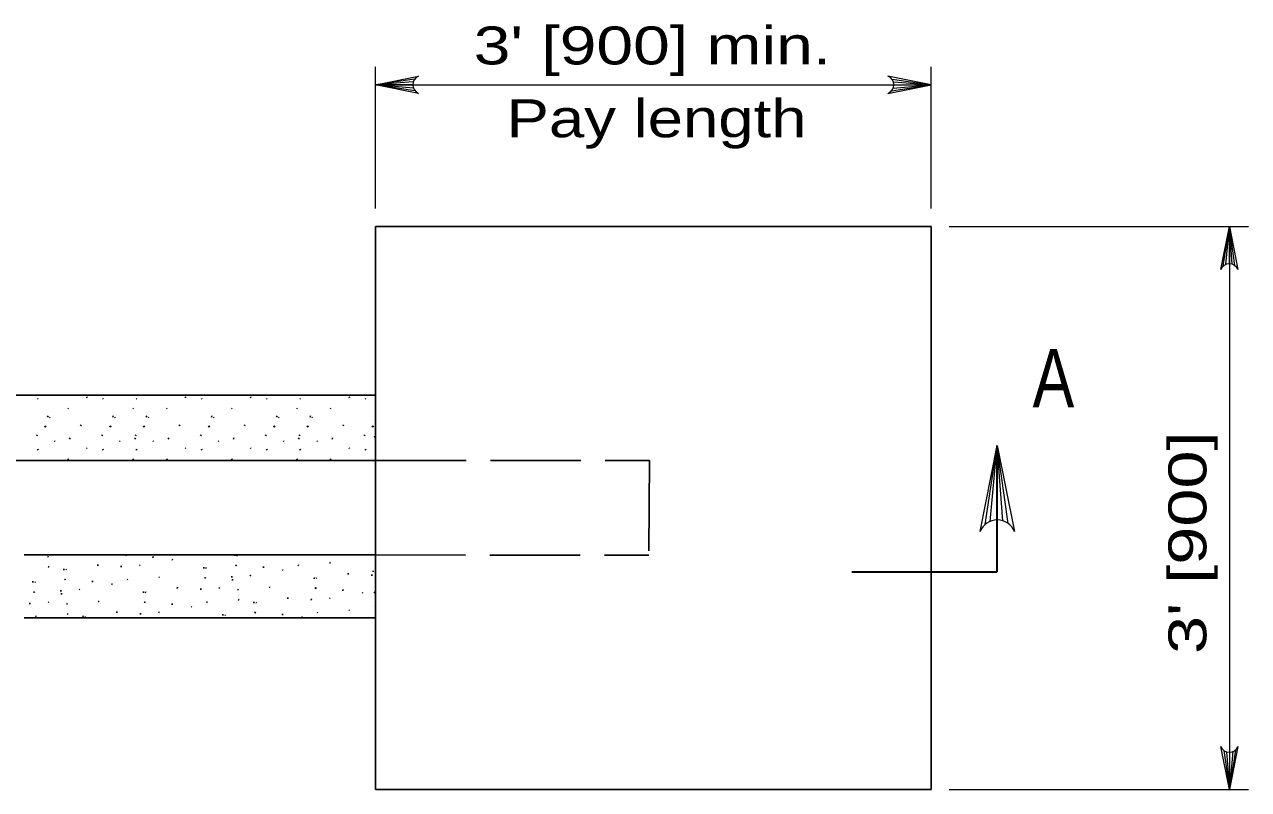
# Model space of a CAD drawing. Extents: x 1083.1 to 1117.1, y 697.4 to 741.4.
# Drawn here: x 1097.48 to 1102.51, y 711.45 to 714.6 of the extents above; entities that cross this region are included whole.
import ezdxf
from ezdxf.enums import TextEntityAlignment as Align

# ---------------------------------------------------------------- set-up
doc = ezdxf.new("R2010")
doc.units = 0
doc.header["$LTSCALE"] = 0.062
doc.linetypes.add('LONG_DASHED', pattern=[7.5, 6, -1.5])
doc.layers.add('1', color=7, linetype='Continuous', lineweight=13)

msp = doc.modelspace()

# ---------------------------------------------------------------- linework, layer by layer
at = {"layer": '1'}
for p, q in [((1098.92075, 713.84025), (1098.92075, 714.42317)), ((1101.20325, 713.84025), (1101.20325, 714.42317)), ((1099.081, 714.37175), (1098.92075, 714.34933)), ((1099.0755, 714.36067), (1098.92075, 714.34933)), ((1098.92075, 714.34933), (1101.20325, 714.34933)), ((1099.07392, 714.34933), (1098.92075, 714.34933)), ((1099.07675, 714.33492), (1098.92075, 714.34933)), ((1099.08283, 714.32458), (1098.92075, 714.34933)), ((1101.04108, 714.32458), (1101.20325, 714.34933)), ((1101.043, 714.37175), (1101.20325, 714.34933)), ((1101.04725, 714.33492), (1101.20325, 714.34933)), ((1101.04842, 714.36067), (1101.20325, 714.34933)), ((1101.05008, 714.34933), (1101.20325, 714.34933)), ((1101.277, 713.76642), (1102.50758, 713.76642)), ((1102.40408, 713.60433), (1102.42892, 713.76642)), ((1102.4145, 713.61042), (1102.42892, 713.76642)), ((1102.42892, 713.76642), (1102.42892, 711.45225)), ((1102.42892, 713.61325), (1102.42892, 713.76642)), ((1102.44025, 713.61158), (1102.42892, 713.76642)), ((1102.45133, 713.60617), (1102.42892, 713.76642)), ((1101.42575, 712.54217), (1101.47533, 712.86642)), ((1101.44658, 712.55442), (1101.47533, 712.86642)), ((1101.47533, 712.56008), (1101.47533, 712.86642)), ((1101.498, 712.55675), (1101.47533, 712.86642)), ((1101.52017, 712.54592), (1101.47533, 712.86642)), ((1102.4065, 711.61242), (1102.42892, 711.45225)), ((1102.41758, 711.607), (1102.42892, 711.45225)), ((1102.45367, 711.61433), (1102.42892, 711.45225)), ((1102.44333, 711.60825), (1102.42892, 711.45225)), ((1102.42892, 711.60542), (1102.42892, 711.45225)), ((1101.277, 711.45225), (1102.50758, 711.45225))]:
    msp.add_line(p, q, dxfattribs=at)
at = {"layer": '1', "lineweight": 25}
for p, q in [((1098.92075, 713.76642), (1098.92075, 713.07375)), ((1098.92075, 713.07375), (1097.47983, 713.07375)), ((1097.53225, 713.06008), (1097.5345, 713.05683)), ((1097.73392, 713.06617), (1097.73617, 713.06283)), ((1097.79992, 713.06008), (1097.80225, 713.05683)), ((1097.93742, 713.06008), (1097.93975, 713.05683)), ((1098.13917, 713.06617), (1098.14133, 713.06283)), ((1098.20517, 713.06008), (1098.20742, 713.05683)), ((1098.40683, 713.06617), (1098.40908, 713.06283)), ((1098.47283, 713.06008), (1098.47517, 713.05683)), ((1098.61033, 713.06008), (1098.61267, 713.05683)), ((1098.81208, 713.06617), (1098.81425, 713.06283)), ((1098.87808, 713.06008), (1098.88033, 713.05683)), ((1097.5735, 712.98292), (1097.57575, 712.988)), ((1097.58167, 712.98292), (1097.58392, 712.97967)), ((1097.65658, 713.0205), (1097.65892, 713.01708)), ((1097.84125, 712.98292), (1097.84342, 712.988)), ((1097.84933, 712.98292), (1097.85158, 712.97967)), ((1097.92433, 713.0205), (1097.92658, 713.01708)), ((1097.97875, 712.98292), (1097.98092, 712.988)), ((1097.98683, 712.98292), (1097.98917, 712.97967)), ((1098.06183, 713.0205), (1098.06408, 713.01708)), ((1098.24642, 712.98292), (1098.24867, 712.988)), ((1098.25458, 712.98292), (1098.25683, 712.97967)), ((1098.3295, 713.0205), (1098.33175, 713.01708)), ((1098.51417, 712.98292), (1098.51633, 712.988)), ((1098.52225, 712.98292), (1098.5245, 712.97967)), ((1098.59725, 713.0205), (1098.5995, 713.01708)), ((1098.65167, 712.98292), (1098.65383, 712.988)), ((1098.65975, 712.98292), (1098.662, 712.97967)), ((1098.73475, 713.0205), (1098.737, 713.01708)), ((1098.91933, 712.98292), (1098.92075, 712.98608)), ((1097.56183, 712.947), (1097.564, 712.94358)), ((1097.564, 712.94575), (1097.56625, 712.94233)), ((1097.70933, 712.947), (1097.71158, 712.952)), ((1097.8295, 712.947), (1097.83175, 712.94358)), ((1097.83175, 712.94575), (1097.83392, 712.94233)), ((1097.967, 712.947), (1097.96925, 712.94358)), ((1097.96925, 712.94575), (1097.97142, 712.94233)), ((1098.1145, 712.947), (1098.11683, 712.952)), ((1098.23475, 712.947), (1098.23692, 712.94358)), ((1098.23692, 712.94575), (1098.23917, 712.94233)), ((1098.38225, 712.947), (1098.3845, 712.952)), ((1098.50242, 712.947), (1098.50467, 712.94358)), ((1098.50467, 712.94575), (1098.50683, 712.94233)), ((1098.63992, 712.947), (1098.64217, 712.94358)), ((1098.64217, 712.94575), (1098.64433, 712.94233)), ((1098.78742, 712.947), (1098.78975, 712.952)), ((1098.90767, 712.947), (1098.90983, 712.94358)), ((1098.90983, 712.94575), (1098.912, 712.94233)), ((1097.52875, 712.9055), (1097.53108, 712.91058)), ((1097.6015, 712.88617), (1097.60375, 712.88283)), ((1097.66408, 712.89267), (1097.66625, 712.89775)), ((1097.7965, 712.9055), (1097.79875, 712.91058)), ((1097.86925, 712.88617), (1097.87142, 712.88283)), ((1097.93175, 712.89267), (1097.934, 712.89775)), ((1097.934, 712.9055), (1097.93625, 712.91058)), ((1098.00675, 712.88617), (1098.00892, 712.88283)), ((1098.06925, 712.89267), (1098.0715, 712.89775)), ((1098.20167, 712.9055), (1098.20392, 712.91058)), ((1098.27442, 712.88617), (1098.27667, 712.88283)), ((1098.337, 712.89267), (1098.33917, 712.89775)), ((1098.46942, 712.9055), (1098.47167, 712.91058)), ((1098.54217, 712.88617), (1098.54433, 712.88283)), ((1098.60467, 712.89267), (1098.60692, 712.89775)), ((1098.60692, 712.9055), (1098.60917, 712.91058)), ((1098.67967, 712.88617), (1098.68183, 712.88283)), ((1098.74217, 712.89267), (1098.74442, 712.89775)), ((1098.87458, 712.9055), (1098.87692, 712.91058)), ((1098.91683, 712.905), (1098.91742, 712.9)), ((1097.53225, 712.85083), (1097.5345, 712.84758)), ((1097.73392, 712.85692), (1097.73617, 712.85358)), ((1097.79992, 712.85083), (1097.80225, 712.84758)), ((1097.93742, 712.85083), (1097.93975, 712.84758)), ((1098.13917, 712.85692), (1098.14133, 712.85358)), ((1098.20517, 712.85083), (1098.20742, 712.84758)), ((1098.40683, 712.85692), (1098.40908, 712.85358)), ((1098.47283, 712.85083), (1098.47517, 712.84758)), ((1098.61033, 712.85083), (1098.61267, 712.84758)), ((1098.81208, 712.85692), (1098.81425, 712.85358)), ((1098.87808, 712.85083), (1098.88033, 712.84758)), ((1097.65658, 712.81117), (1097.65892, 712.80783)), ((1097.92433, 712.81117), (1097.92658, 712.80783)), ((1098.06183, 712.81117), (1098.06408, 712.80783)), ((1098.3295, 712.81117), (1098.33175, 712.80783)), ((1098.59725, 712.81117), (1098.5995, 712.80783)), ((1098.73475, 712.81117), (1098.737, 712.80783)), ((1098.92075, 712.41658), (1097.47717, 712.41658)), ((1097.49867, 712.41658), (1097.50008, 712.41558)), ((1097.57325, 712.41067), (1097.57658, 712.4085)), ((1097.77983, 712.37217), (1097.78008, 712.37767)), ((1097.87617, 712.36633), (1097.87642, 712.37192)), ((1097.89208, 712.41658), (1097.89458, 712.41483)), ((1097.89417, 712.41658), (1097.89708, 712.4145)), ((1097.95092, 712.37567), (1097.95417, 712.37333)), ((1098.00642, 712.40517), (1098.00658, 712.41067)), ((1098.08458, 712.39817), (1098.08792, 712.39592)), ((1098.14908, 712.41658), (1098.15142, 712.41508)), ((1098.34275, 712.41267), (1098.34292, 712.41658)), ((1098.34533, 712.37492), (1098.34867, 712.37267)), ((1098.34783, 712.37458), (1098.35117, 712.37233)), ((1098.35025, 712.41575), (1098.35367, 712.4135)), ((1098.60217, 712.375), (1098.6055, 712.37283)), ((1098.73233, 712.38483), (1098.73575, 712.38258)), ((1098.92017, 712.3815), (1098.92075, 712.38108)), ((1097.57592, 712.369), (1097.57933, 712.36675)), ((1097.64042, 712.35458), (1097.64058, 712.36008)), ((1097.648, 712.35767), (1097.65133, 712.35542)), ((1098.03, 712.32675), (1098.03342, 712.3245)), ((1098.21525, 712.36117), (1098.21542, 712.36667)), ((1098.21783, 712.32342), (1098.22117, 712.32117)), ((1098.22042, 712.32308), (1098.22367, 712.32075)), ((1098.22275, 712.36417), (1098.22617, 712.362)), ((1098.33025, 712.32417), (1098.3305, 712.32967)), ((1098.405, 712.33342), (1098.40825, 712.33117)), ((1098.4605, 712.36292), (1098.46067, 712.36842)), ((1098.53867, 712.35592), (1098.542, 712.35367)), ((1098.66933, 712.31892), (1098.6695, 712.32442)), ((1098.67683, 712.322), (1098.68025, 712.31975)), ((1098.80875, 712.3365), (1098.80892, 712.342)), ((1098.90508, 712.33067), (1098.90533, 712.33625)), ((1098.91058, 712.35158), (1098.91108, 712.34658)), ((1097.513, 712.30308), (1097.51317, 712.30858)), ((1097.5205, 712.30617), (1097.52383, 712.30392)), ((1097.62792, 712.26608), (1097.62817, 712.27158)), ((1097.64308, 712.31692), (1097.64633, 712.31458)), ((1097.64558, 712.31658), (1097.64892, 712.31425)), ((1097.70267, 712.27542), (1097.706, 712.27308)), ((1097.75825, 712.30483), (1097.75833, 712.31033)), ((1097.83642, 712.29783), (1097.83967, 712.29558)), ((1097.89983, 712.31692), (1097.90325, 712.31475)), ((1098.10642, 712.27842), (1098.10667, 712.28392)), ((1098.20275, 712.27267), (1098.203, 712.27817)), ((1098.2775, 712.28192), (1098.28083, 712.27967)), ((1098.333, 712.31142), (1098.33317, 712.31692)), ((1098.35392, 712.27475), (1098.35733, 712.2725)), ((1098.48408, 712.28458), (1098.4875, 712.28233)), ((1098.672, 712.28125), (1098.67525, 712.27892)), ((1098.6745, 712.28092), (1098.67775, 712.27858)), ((1098.78708, 712.26917), (1098.78725, 712.27467)), ((1097.5005, 712.21458), (1097.50067, 712.22008)), ((1097.51558, 712.26542), (1097.51883, 712.26308)), ((1097.51808, 712.265), (1097.52142, 712.26275)), ((1097.57517, 712.22392), (1097.5785, 712.22158)), ((1097.63075, 712.25333), (1097.63083, 712.25883)), ((1097.78183, 712.2265), (1097.78517, 712.22425)), ((1097.96708, 712.26092), (1097.96725, 712.26633)), ((1097.96967, 712.22317), (1097.973, 712.22083)), ((1097.97217, 712.22283), (1097.9755, 712.2205)), ((1097.97458, 712.26392), (1097.97792, 712.26175)), ((1098.22642, 712.22325), (1098.22983, 712.221)), ((1098.35658, 712.23308), (1098.36, 712.23075)), ((1098.42117, 712.21867), (1098.42133, 712.22417)), ((1098.42867, 712.22167), (1098.432, 712.2195)), ((1098.5605, 712.23617), (1098.56075, 712.24167)), ((1098.65683, 712.23042), (1098.65708, 712.23592)), ((1098.73158, 712.23975), (1098.73492, 712.23742)), ((1098.86533, 712.26217), (1098.86858, 712.25992)), ((1098.91567, 712.25933), (1098.918, 712.26433)), ((1097.65167, 712.21667), (1097.655, 712.2145)), ((1097.65433, 712.175), (1097.65767, 712.17275)), ((1097.85825, 712.17817), (1097.85842, 712.18367)), ((1097.95458, 712.17233), (1097.95475, 712.17783)), ((1098.02925, 712.18167), (1098.03258, 712.17933)), ((1098.08483, 712.21117), (1098.085, 712.21667)), ((1098.163, 712.20408), (1098.16625, 712.20192)), ((1098.29367, 712.16717), (1098.29383, 712.17267)), ((1098.30117, 712.17017), (1098.3045, 712.168)), ((1098.42375, 712.18092), (1098.42708, 712.17867)), ((1098.42625, 712.18058), (1098.42958, 712.17825)), ((1098.53892, 712.16892), (1098.53908, 712.17442)), ((1098.68058, 712.181), (1098.68392, 712.17883)), ((1098.81075, 712.19083), (1098.81408, 712.18858)), ((1098.91917, 712.20475), (1098.92075, 712.20233)), ((1097.52417, 712.16517), (1097.5275, 712.163)), ((1097.71883, 712.16058), (1097.719, 712.16608)), ((1097.72633, 712.16367), (1097.72975, 712.16142)), ((1098.61708, 712.16192), (1098.62033, 712.15967)), ((1098.92075, 712.15767), (1098.92075, 711.45225)), ((1098.92075, 711.45225), (1101.20325, 711.45225))]:
    msp.add_line(p, q, dxfattribs=at)
at = {"layer": '1', "lineweight": 35}
for p, q in [((1101.47533, 712.34717), (1101.47533, 712.86642)), ((1100.87808, 712.34717), (1101.47533, 712.34717))]:
    msp.add_line(p, q, dxfattribs=at)
at = {"layer": '1', "linetype": 'LONG_DASHED', "lineweight": 25}
for p, q in [((1098.92075, 712.80517), (1100.04708, 712.80525)), ((1100.04708, 712.80525), (1100.04425, 712.4155)), ((1098.918, 712.41658), (1100.04425, 712.4155))]:
    msp.add_line(p, q, dxfattribs=at)
at = {"layer": '1'}
for points in [[(1099.09775, 714.31392), (1098.92075, 714.34933), (1099.09775, 714.38475)], [(1101.02625, 714.31392), (1101.20325, 714.34933), (1101.02625, 714.38475)], [(1102.3935, 713.58942), (1102.42892, 713.76642), (1102.46433, 713.58942)], [(1101.40458, 712.51242), (1101.47533, 712.86642), (1101.54617, 712.51242)], [(1102.46433, 711.62925), (1102.42892, 711.45225), (1102.3935, 711.62925)]]:
    msp.add_lwpolyline(points, dxfattribs=at)
at = {"layer": '1', "lineweight": 25}
for points in [[(1098.92075, 713.76642), (1101.20325, 713.76642), (1101.20325, 711.45225)], [(1097.47983, 713.07375), (1090.79808, 713.07375), (1090.79808, 712.80517), (1097.47983, 712.80517)], [(1097.47717, 712.15767), (1098.92075, 712.15767), (1098.92075, 713.07375), (1098.92075, 712.41658)], [(1097.47983, 712.80517), (1098.92075, 712.80517), (1098.92075, 713.07375)]]:
    msp.add_lwpolyline(points, dxfattribs=at)
at = {"layer": '1'}
for centre, radius, start, end in [((1099.11202, 714.34939), 0.0382, 112.08782, 247.91395), ((1101.01194, 714.34939), 0.0382, 292.08605, 67.91218), ((1102.42894, 713.57514), 0.0382, 22.08782, 157.91395), ((1101.47542, 712.48382), 0.0764, 22.08782, 157.91395), ((1102.42886, 711.64351), 0.0382, 202.08782, 337.91395)]:
    msp.add_arc(centre, radius, start, end, dxfattribs=at)

# ---------------------------------------------------------------- texts
for s, width, p in [("3' [900] min.", 1.3, (1100.05854, 714.43283)), ('Pay length', 1.25, (1100.07546, 714.13342))]:
    msp.add_text(s, height=0.156, dxfattribs=dict(at, width=width)).set_placement(p, align=Align.CENTER)
at = {"layer": '1', "width": 0.8}
msp.add_text('A', height=0.24, dxfattribs=at).set_placement((1101.62025, 713.02325))
at = {"layer": '1', "width": 1.35}
msp.add_text("3' [900]", height=0.156, rotation=90, dxfattribs=at).set_placement((1102.33442, 712.00933))

doc.saveas('drawing.dxf')
